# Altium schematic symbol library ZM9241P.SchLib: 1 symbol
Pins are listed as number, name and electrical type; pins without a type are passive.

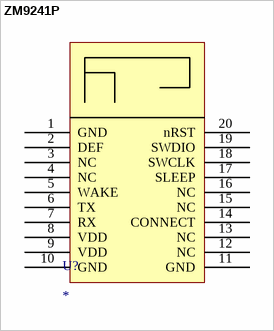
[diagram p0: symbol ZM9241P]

## ZM9241P
designator U?
pins: 1 GND, 2 DEF, 3 NC, 4 NC, 5 WAKE, 6 TX, 7 RX, 8 VDD, 9 VDD, 10 GND, 11 GND, 12 NC, 13 NC, 14 CONNECT, 15 NC, 16 NC, 17 SLEEP, 18 SWCLK, 19 SWDIO, 20 nRST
